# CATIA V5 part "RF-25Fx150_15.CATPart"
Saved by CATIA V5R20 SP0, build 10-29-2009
Part number: _RF-25Fx150
Definition: NONE
Nomenclature: _RF-25Fx150
Source: Unknown
Description: PART-_RF-25Fx150-DESC
Bounding box of the stored display mesh (mm): x -150 to 33.5, y -13.25 to 13.25, z -13.25 to 13.25
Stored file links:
  C:\Users\Utente\Desktop\IO LAVORO\3D X SITO CF\X SITO\PLASTICA\RFF\RF-25Fx150_15.CATPart

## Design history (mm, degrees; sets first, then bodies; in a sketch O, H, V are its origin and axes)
Body1 "_RF-25Fx150" (main body)
  Solid1: solid without history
